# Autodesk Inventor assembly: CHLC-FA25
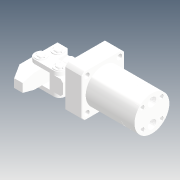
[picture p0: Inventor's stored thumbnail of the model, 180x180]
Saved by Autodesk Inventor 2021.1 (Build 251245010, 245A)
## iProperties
Created: 2019-04
Part Number: CHLC-FA25
Description: STEP AP214
Document SubType Name: Assembly
Designer: user
Title: CHLC-FA25.STEP
Revision Number: ÈÎºÎ
Sending System: SolidWorks 2016
Preprocessor: SwSTEP 2.0
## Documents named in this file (12)
- D:\Vault_2016\Projekty\Clamptek\Hydraulic\CHLC\CHLC-25\Inventor\CHLC-FA25\CHLC-FA25.iam
- D:\Vault_2016\Projekty\Clamptek\Hydraulic\CHLC\CHLC-25\Inventor\CHLC-FA25\CHLC-FA25_ASM.ipt
- D:\Vault_2016\Projekty\Clamptek\Hydraulic\CHLC\CHLC-25\Inventor\CHLC-FA25\CHLC-FA25BT.ipt
- D:\Vault_2016\Projekty\Clamptek\Hydraulic\CHLC\CHLC-25\Inventor\CHLC-FA25\CHLC-FA25HG.ipt
- D:\Vault_2016\Projekty\Clamptek\Hydraulic\CHLC\CHLC-25\Inventor\CHLC-FA25\M6.ipt
- D:\Vault_2016\Projekty\Clamptek\Hydraulic\CHLC\CHLC-25\Inventor\CHLC-FA25\CHLC-25ZC.ipt
- D:\Vault_2016\Projekty\Clamptek\Hydraulic\CHLC\CHLC-25\Inventor\CHLC-FA25\CHLC-25LG.ipt
- D:\Vault_2016\Projekty\Clamptek\Hydraulic\CHLC\CHLC-25\Inventor\CHLC-FA25\CHLC-25HSG_1.ipt
- D:\Vault_2016\Projekty\Clamptek\Hydraulic\CHLC\CHLC-25\Inventor\CHLC-FA25\CHLC-25DX.ipt
- D:\Vault_2016\Projekty\Clamptek\Hydraulic\CHLC\CHLC-25\Inventor\CHLC-FA25\CHLC-25CX.ipt
- D:\Vault_2016\Projekty\Clamptek\Hydraulic\CHLC\CHLC-25\Inventor\CHLC-FA25\CHLC-25KKDC.ipt
- D:\Vault_2016\Projekty\Clamptek\Hydraulic\CHLC\CHLC-25\Inventor\CHLC-FA25\Ñ¹±Û.ipt
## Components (21 placed, 21 different names)
1. CHLC-FA25_ASM_1
2. CHLC-FA25BT_2
3. CHLC-FA25HG_3
4. M6_4
5. M6_5
6. M6_6
7. M6_7
8. CHLC-25ZC_8
9. CHLC-25LG_9
10. CHLC-25LG_10
11. CHLC-25HSG_1_11
12. CHLC-25DX_12
13. CHLC-25CX_13
14. CHLC-25CX_14
15. CHLC-25KKDC_15
16. CHLC-25KKDC_16
17. CHLC-25KKDC_17
18. CHLC-25KKDC_18
19. CHLC-25KKDC_19
20. CHLC-25KKDC_20
21. Ñ¹±Û_21
